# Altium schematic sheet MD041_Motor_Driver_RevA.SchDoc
size 431 x 279 mm; Date: Not shown in title block; ApprovedBy: Not shown in title block; CheckedBy: Not shown in title block; Author: Not shown in title block; CompanyName: Not shown in title block; Engineer: Not shown in title block; Organization: Not shown in title block; Address1: Not shown in title block; Address2: Not shown in title block; Address3: Not shown in title block; Address4: Not shown in title block; DocumentNumber: 2; Revision: Use project parameter SCH_Rev; SheetNumber: 1; SheetTotal: 4; PageSetup: Record=PageOptions¦CenterHorizontal=True¦CenterVertical=True¦PrintScale=1.00¦XCorrection=1.00¦YCorrection=1.00¦PrintKind=0¦BorderSize=5000000¦LeftOffset=0¦BottomOffset=0¦Orientation=2¦PaperLength=1000¦PaperWidth=1000¦Scale=100¦PaperSource=15¦PrintQuality=600¦MediaType=1¦DitherType=10¦PaperKind=Letter¦PrintScaleMode=1
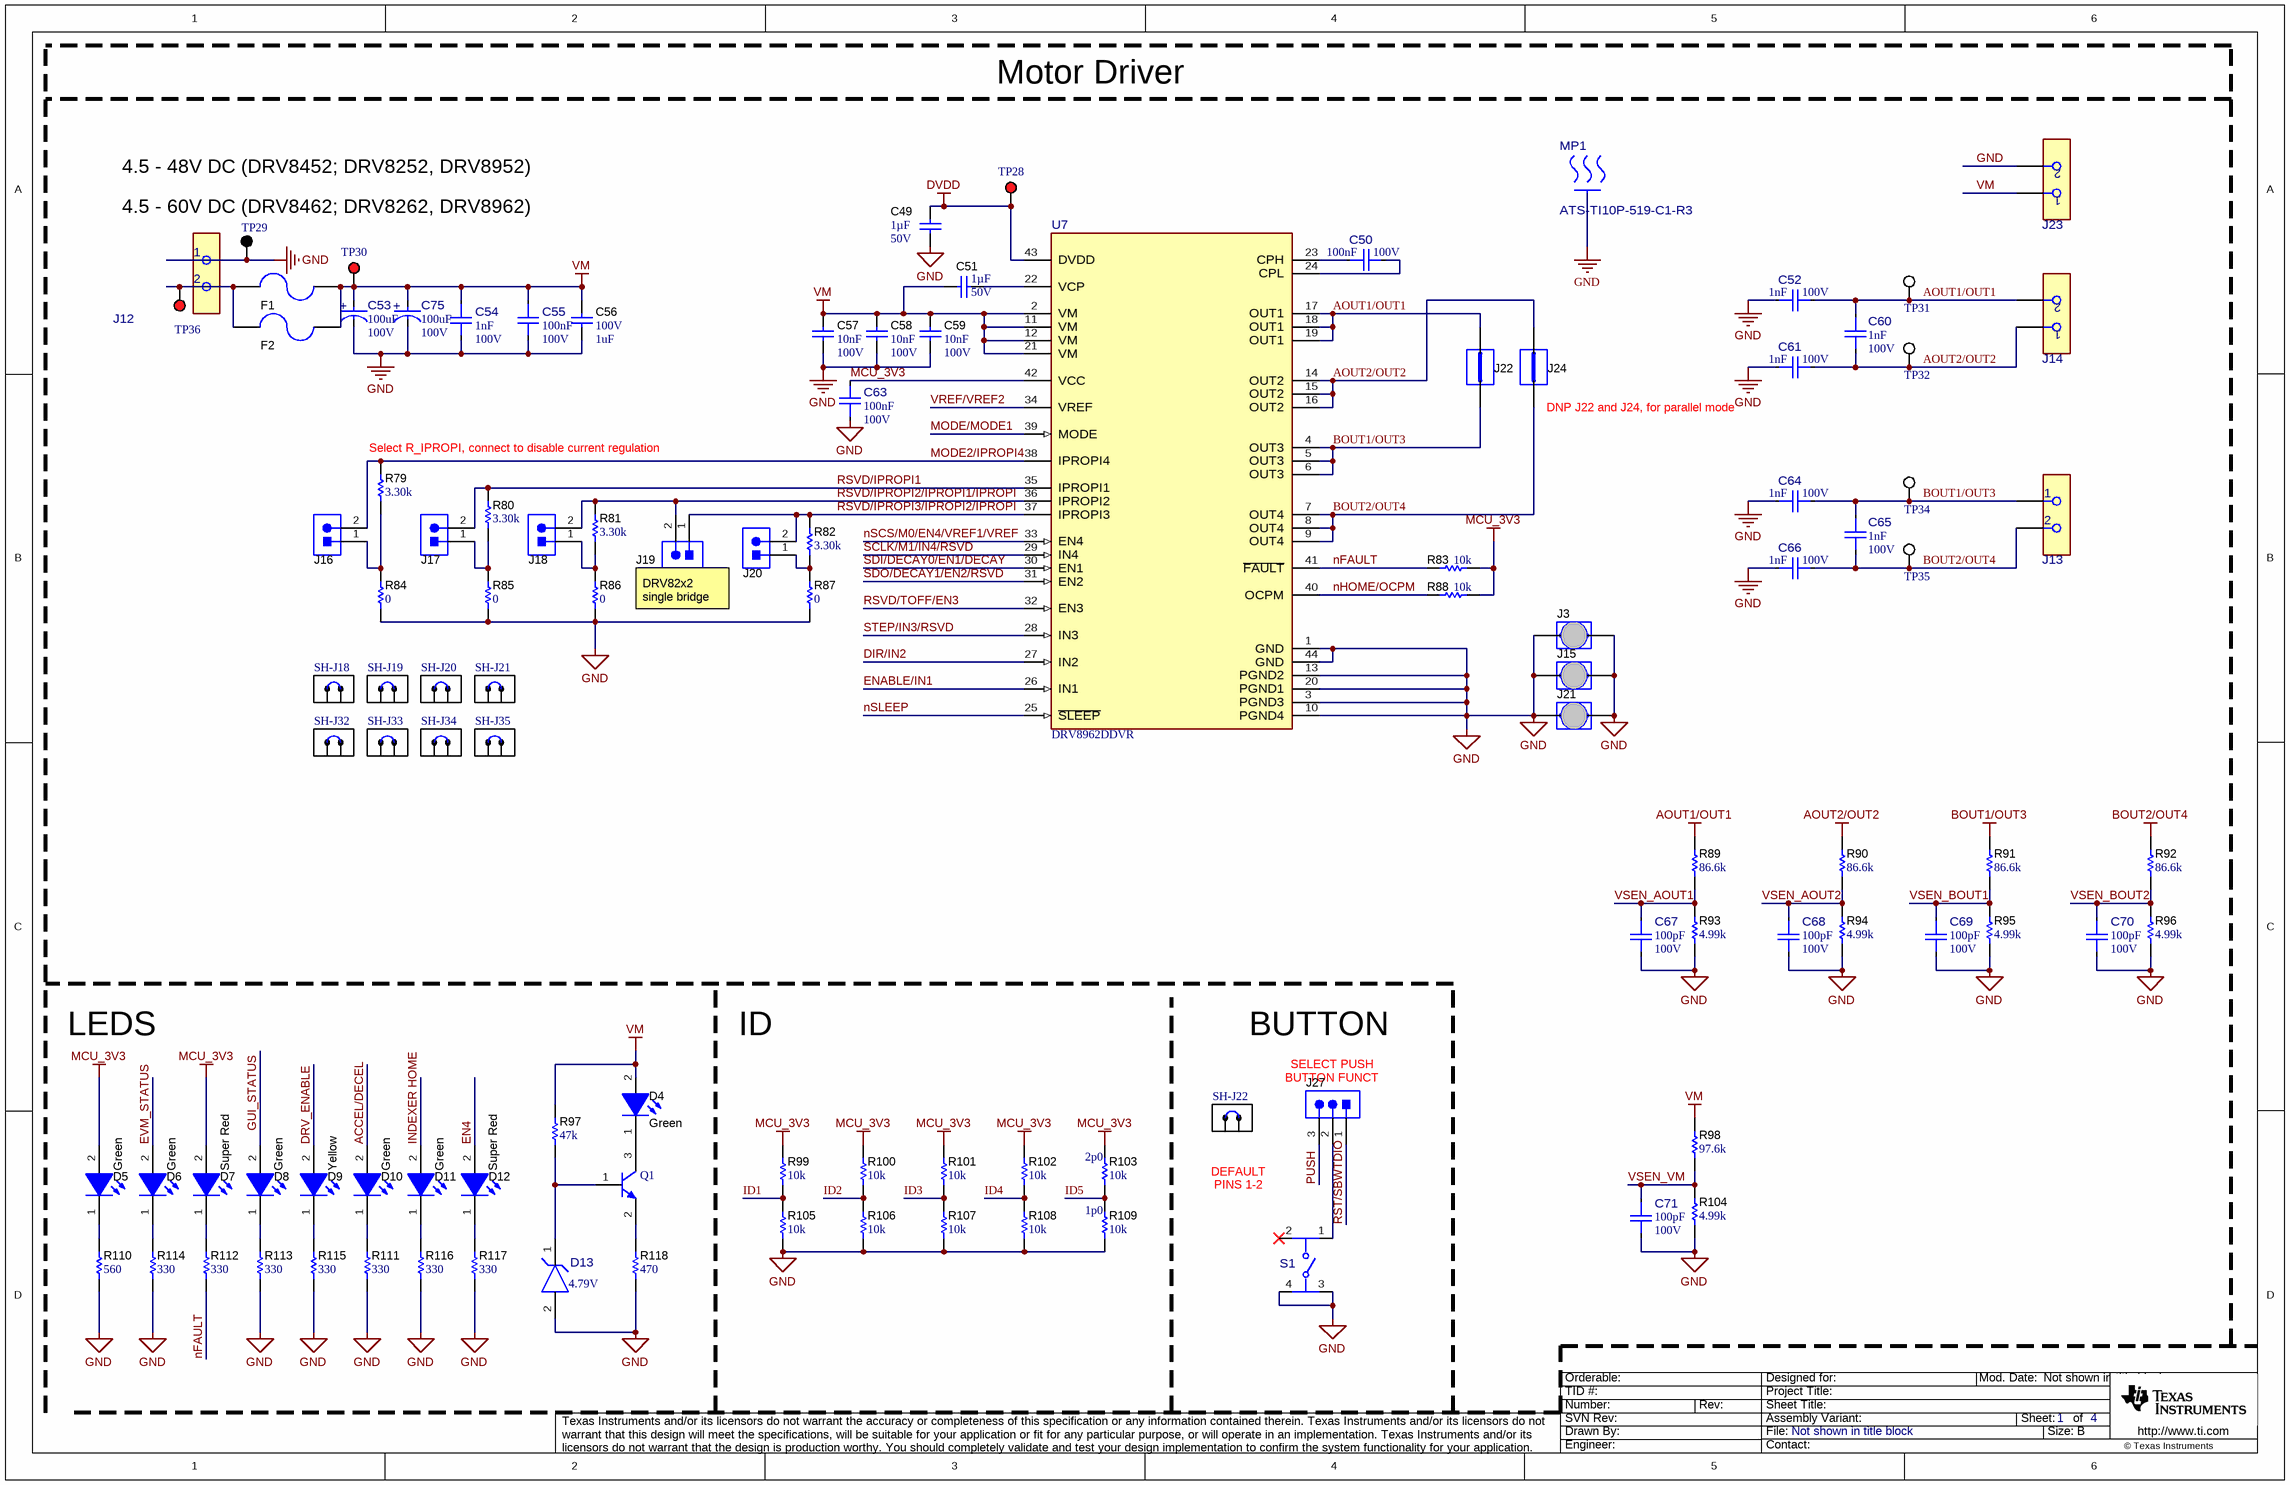
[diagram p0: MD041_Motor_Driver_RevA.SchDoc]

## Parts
C49  Cap_F: 1µF  VDC_V: 50V  [0805_HV]  (hidden comment: C2012X7R1H105K125AB)
C50  Cap_F: 100nF  VDC_V: 100V  [FP-885012206120_0603-MFG]  (hidden comment: 885012206120)
C51  Cap_F: 1µF  VDC_V: 50V  [0805_HV]  (hidden comment: C2012X7R1H105K125AB)
C52  ValueDisplayed: 1nF  VDC_V: 100V  [FP-885012006085_0603-MFG]  (hidden comment: 885012006085)
C53  ValueDisplayed: 100uF  VDC_V: 100V  [FP-EMVY101ARA101MKE0S_RADIAL-MFG]  (hidden comment: EMVY101ARA101MKE0S)
C54  ValueDisplayed: 1nF  VDC_V: 100V  [FP-885012006085_0603-MFG]  (hidden comment: 885012006085)
C55  Cap_F: 100nF  VDC_V: 100V  [FP-885012206120_0603-MFG]  (hidden comment: 885012206120)
C56  VDC_V: 100V  ValueDisplayed: 1uF  [1210_220]  (hidden comment: CGA6M2X7R2A105K200AA)
C57  Cap_F: 10nF  VDC_V: 100V  [0603L]  (hidden comment: 885012206114)
C58  Cap_F: 10nF  VDC_V: 100V  [0603L]  (hidden comment: 885012206114)
C59  Cap_F: 10nF  VDC_V: 100V  [0603L]  (hidden comment: 885012206114)
C60  ValueDisplayed: 1nF  VDC_V: 100V  [FP-885012006085_0603-MFG]  (hidden comment: 885012006085)
C61  ValueDisplayed: 1nF  VDC_V: 100V  [FP-885012006085_0603-MFG]  (hidden comment: 885012006085)
C63  Cap_F: 100nF  VDC_V: 100V  [FP-885012206120_0603-MFG]  (hidden comment: 885012206120)
C64  ValueDisplayed: 1nF  VDC_V: 100V  [FP-885012006085_0603-MFG]  (hidden comment: 885012006085)
C65  ValueDisplayed: 1nF  VDC_V: 100V  [FP-885012006085_0603-MFG]  (hidden comment: 885012006085)
C66  ValueDisplayed: 1nF  VDC_V: 100V  [FP-885012006085_0603-MFG]  (hidden comment: 885012006085)
C67  ValueDisplayed: 100pF  VDC_V: 100V  [FP-885012005080_0402-MFG]  (hidden comment: 885012005080)
C68  ValueDisplayed: 100pF  VDC_V: 100V  [FP-885012005080_0402-MFG]  (hidden comment: 885012005080)
C69  ValueDisplayed: 100pF  VDC_V: 100V  [FP-885012005080_0402-MFG]  (hidden comment: 885012005080)
C70  ValueDisplayed: 100pF  VDC_V: 100V  [FP-885012005080_0402-MFG]  (hidden comment: 885012005080)
C71  ValueDisplayed: 100pF  VDC_V: 100V  [FP-885012005080_0402-MFG]  (hidden comment: 885012005080)
C75  ValueDisplayed: 100uF  VDC_V: 100V  [FP-EMVY101ARA101MKE0S_RADIAL-MFG]  (hidden comment: EMVY101ARA101MKE0S)
D4  value Green  [WL-SMCW_GREEN]  (hidden comment: 150060VS75000)
D5  value Green  [WL-SMCW_GREEN]  (hidden comment: 150060VS75000)
D6  value Green  [WL-SMCW_GREEN]  (hidden comment: 150060VS75000)
D7  value Super Red  [WL-SMCW_RED]  (hidden comment: 150060SS75000)
D8  value Green  [WL-SMCW_GREEN]  (hidden comment: 150060VS75000)
D9  value Yellow  [WL-SMCW_YELLOW]  (hidden comment: 150060YS75000)
D10  value Green  [WL-SMCW_GREEN]  (hidden comment: 150060VS75000)
D11  value Green  [WL-SMCW_GREEN]  (hidden comment: 150060VS75000)
D12  value Super Red  [WL-SMCW_RED]  (hidden comment: 150060SS75000)
D13  Vf_V: 4.79V  [FP-BZX84J-B4V7,115_SC90-MFG]  (hidden comment: BZX84J-B4V7,115)
F1  0463015.ER  [Fuse_0463]  (value not drawn)
F2  0463015.ER  [Fuse_0463]  (value not drawn)
J3  D3082-05  [Harwin_D3082-05]  (value not drawn)
J12  691256610002  [FP-691256610002_HDR2-MFG]  (value not drawn)
J13  691250610002  [FP-691250610002_CONN_TERM_BLOCK2-MFG]  (value not drawn)
J14  691250610002  [FP-691250610002_CONN_TERM_BLOCK2-MFG]  (value not drawn)
J15  D3082-05  [Harwin_D3082-05]  (value not drawn)
J16  PBC02SAAN  [Sullins_PBC02SAAN]  (value not drawn)
J17  PBC02SAAN  [Sullins_PBC02SAAN]  (value not drawn)
J18  PBC02SAAN  [Sullins_PBC02SAAN]  (value not drawn)
J19  PBC02SAAN  [Sullins_PBC02SAAN]  (value not drawn)
J20  PBC02SAAN  [Sullins_PBC02SAAN]  (value not drawn)
J21  D3082-05  [Harwin_D3082-05]  (value not drawn)
J22  D3082-05  [Harwin_D3082-05]  (value not drawn)
J23  691250610002  [FP-691250610002_CONN_TERM_BLOCK2-MFG]  (value not drawn)
J24  D3082-05  [Harwin_D3082-05]  (value not drawn)
J27  61300311121  [WURTH_61300311121]  (value not drawn)
MP1  ATS-TI10P-519-C1-R3  [FP-ATS-TI10P-519-C1-R3_HEAT_SINK-MFG]
Q1  BC846BLT1G  [ONSC-SOT-23-3-318-08_V]  (value not drawn)
R79  ValueDisplayed: 3.30k  [0402L]  (hidden comment: ERJ-2RKF3301X)
R80  ValueDisplayed: 3.30k  [0402L]  (hidden comment: ERJ-2RKF3301X)
R81  ValueDisplayed: 3.30k  [0402L]  (hidden comment: ERJ-2RKF3301X)
R82  ValueDisplayed: 3.30k  [0402L]  (hidden comment: ERJ-2RKF3301X)
R83  ValueDisplayed: 10k  [0603L]  (hidden comment: RC0603JR-0710KL)
R84  ValueDisplayed: 0  [0402]  (hidden comment: CRCW04020000Z0EDHP)
R85  ValueDisplayed: 0  [0402]  (hidden comment: CRCW04020000Z0EDHP)
R86  ValueDisplayed: 0  [0402]  (hidden comment: CRCW04020000Z0EDHP)
R87  ValueDisplayed: 0  [0402]  (hidden comment: CRCW04020000Z0EDHP)
R88  ValueDisplayed: 10k  [0603L]  (hidden comment: RC0603JR-0710KL)
R89  ValueDisplayed: 86.6k  [0603L]  (hidden comment: CRCW060386K6FKEA)
R90  ValueDisplayed: 86.6k  [0603L]  (hidden comment: CRCW060386K6FKEA)
R91  ValueDisplayed: 86.6k  [0603L]  (hidden comment: CRCW060386K6FKEA)
R92  ValueDisplayed: 86.6k  [0603L]  (hidden comment: CRCW060386K6FKEA)
R93  ValueDisplayed: 4.99k  [0603L]  (hidden comment: CRCW06034K99FKEA)
R94  ValueDisplayed: 4.99k  [0603L]  (hidden comment: CRCW06034K99FKEA)
R95  ValueDisplayed: 4.99k  [0603L]  (hidden comment: CRCW06034K99FKEA)
R96  ValueDisplayed: 4.99k  [0603L]  (hidden comment: CRCW06034K99FKEA)
R97  ValueDisplayed: 47k  [0402]  (hidden comment: CRCW040247K0JNED)
R98  ValueDisplayed: 97.6k  [0603]  (hidden comment: CRCW060397K6FKEA)
R99  ValueDisplayed: 10k  [0603L]  (hidden comment: RC0603JR-0710KL)
R100  ValueDisplayed: 10k  [0603L]  (hidden comment: RC0603JR-0710KL)
R101  ValueDisplayed: 10k  [0603L]  (hidden comment: RC0603JR-0710KL)
R102  ValueDisplayed: 10k  [0603L]  (hidden comment: RC0603JR-0710KL)
R103  ValueDisplayed: 10k  [0603L]  (hidden comment: RC0603JR-0710KL)
R104  ValueDisplayed: 4.99k  [0603L]  (hidden comment: CRCW06034K99FKEA)
R105  ValueDisplayed: 10k  [0603L]  (hidden comment: RC0603JR-0710KL)
R106  ValueDisplayed: 10k  [0603L]  (hidden comment: RC0603JR-0710KL)
R107  ValueDisplayed: 10k  [0603L]  (hidden comment: RC0603JR-0710KL)
R108  ValueDisplayed: 10k  [0603L]  (hidden comment: RC0603JR-0710KL)
R109  ValueDisplayed: 10k  [0603L]  (hidden comment: RC0603JR-0710KL)
R110  ValueDisplayed: 560  [0603]  (hidden comment: RC0603FR-07560RL)
R111  ValueDisplayed: 330  [0603L]  (hidden comment: Resistor)
R112  ValueDisplayed: 330  [0603L]  (hidden comment: Resistor)
R113  ValueDisplayed: 330  [0603L]  (hidden comment: Resistor)
R114  ValueDisplayed: 330  [0603L]  (hidden comment: Resistor)
R115  ValueDisplayed: 330  [0603L]  (hidden comment: Resistor)
R116  ValueDisplayed: 330  [0603L]  (hidden comment: Resistor)
R117  ValueDisplayed: 330  [0603L]  (hidden comment: Resistor)
R118  ValueDisplayed: 470  [0603]  (hidden comment: RC0603FR-07470RL)
S1  430481025816  [FP-430481025816_SMT_SW_6MM2_6MM2-MFG]  (value not drawn)
SH-J18  60900213421  [Wurth_60900213421]  (value not drawn)
SH-J19  60900213421  [Wurth_60900213421]  (value not drawn)
SH-J20  60900213421  [Wurth_60900213421]  (value not drawn)
SH-J21  60900213421  [Wurth_60900213421]  (value not drawn)
SH-J22  60900213421  [Wurth_60900213421]  (value not drawn)
SH-J32  60900213421  [Wurth_60900213421]  (value not drawn)
SH-J33  60900213421  [Wurth_60900213421]  (value not drawn)
SH-J34  60900213421  [Wurth_60900213421]  (value not drawn)
SH-J35  60900213421  [Wurth_60900213421]  (value not drawn)
TP28  5010  [Keystone5010]  (value not drawn)
TP29  5011  [Keystone5011]  (value not drawn)
TP30  5010  [Keystone5010]  (value not drawn)
TP31  5015  [Testpoint_Keystone_Miniature]  (value not drawn)
TP32  5015  [Testpoint_Keystone_Miniature]  (value not drawn)
TP34  5015  [Testpoint_Keystone_Miniature]  (value not drawn)
TP35  5015  [Testpoint_Keystone_Miniature]  (value not drawn)
TP36  5010  [Keystone5010]  (value not drawn)
U7  DRV8962DDVR  [DDV0044E-MFG]

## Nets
AOUT1/OUT1: C52.2 C60.1 J14.2 J22.2 R89.2 TP31.1 U7.17(OUT1) U7.18(OUT1) U7.19(OUT1)
AOUT2/OUT2: C60.2 C61.2 J14.1 J24.2 R90.2 TP32.1 U7.14(OUT2) U7.15(OUT2) U7.16(OUT2)
BOUT1/OUT3: C64.2 C65.1 J13.1 J22.1 R91.2 TP34.1 U7.4(OUT3) U7.5(OUT3) U7.6(OUT3)
BOUT2/OUT4: C65.2 C66.2 J13.2 J24.1 R92.2 TP35.1 U7.7(OUT4) U7.8(OUT4) U7.9(OUT4)
DVDD: C49.2 TP28.1 U7.43(DVDD)
GND: C49.1 C52.1 C53.1(CATHODE) C54.2 C55.2 C56.2 C57.2 C58.2 C59.2 C61.1 C63.1 C64.1 C66.1 C67.2 C68.2 C69.2 C70.2 C71.2 C75.1(CATHODE) D13.2(anode) J3.1 J3.2 J12.1 J15.1 J15.2 J21.1 J21.2 J23.2 R84.1 R85.1 R86.1 R87.1 R93.1 R94.1 R95.1 R96.1 R104.1 R105.2 R106.2 R107.2 R108.2 R109.2 R110.1 R111.1 R113.1 R114.1 R115.1 R116.1 R117.1 R118.1 S1.3 S1.4 TP29.1 U7.1(GND) U7.3(PGND3) U7.10(PGND4) U7.13(PGND2) U7.20(PGND1) U7.44(GND)
MCU_3V3: C63.2 D5.2(A) D7.2(A) R83.2 R88.2 R99.1 R100.1 R101.1 R102.1 R103.1 U7.42(VCC)
VM: C51.2 C53.2(ANODE) C54.1 C55.1 C56.1 C57.1 C58.1 C59.1 C75.2(ANODE) D4.2(A) F1.1 F2.1 J23.1 R97.2 R98.2 TP30.1 U7.2(VM) U7.11(VM) U7.12(VM) U7.21(VM)
ACCEL/DECEL: D10.2(A)
DIR/IN2: U7.27(IN2)
DRV_ENABLE: D9.2(A)
EN4: D12.2(A)
ENABLE/IN1: U7.26(IN1)
EVM_STATUS: D6.2(A)
GUI_STATUS: D8.2(A)
ID1: R99.2 R105.1
ID2: R100.2 R106.1
ID3: R101.2 R107.1
ID4: R102.2 R108.1
ID5: R103.2 R109.1
INDEXER HOME: D11.2(A)
MODE2/IPROPI4: J16.2 R79.2 U7.38(IPROPI4)
MODE/MODE1: U7.39(MODE)
nFAULT: R83.1 R112.1 U7.41(~{FAULT})
nHOME/OCPM: R88.1 U7.40(OCPM)
nSCS/M0/EN4/VREF1/VREF: U7.33(EN4)
nSLEEP: U7.25(~{SLEEP})
PUSH: J27.3
RST/SBWTDIO: J27.1
RSVD/IPROPI1: J17.2 R80.2 U7.35(IPROPI1)
RSVD/IPROPI2/IPROPI1/IPROPI: J18.2 J19.2 R81.2 U7.36(IPROPI2)
RSVD/IPROPI3/IPROPI2/IPROPI: J19.1 J20.2 R82.2 U7.37(IPROPI3)
RSVD/TOFF/EN3: U7.32(EN3)
SCLK/M1/IN4/RSVD: U7.29(IN4)
SDI/DECAY0/EN1/DECAY: U7.30(EN1)
SDO/DECAY1/EN2/RSVD: U7.31(EN2)
STEP/IN3/RSVD: U7.28(IN3)
VREF/VREF2: U7.34(VREF)
VSEN_AOUT1: C67.1 R89.1 R93.2
VSEN_AOUT2: C68.1 R90.1 R94.2
VSEN_BOUT1: C69.1 R91.1 R95.2
VSEN_BOUT2: C70.1 R92.1 R96.2
VSEN_VM: C71.1 R98.1 R104.2
NetC50_1: C50.1 U7.23(CPH)
NetC50_2: C50.2 U7.24(CPL)
NetC51_1: C51.1 U7.22(VCP)
NetD4_1: D4.1(K) Q1.3(C)
NetD5_1: D5.1(K) R110.2
NetD6_1: D6.1(K) R114.2
NetD7_1: D7.1(K) R112.2
NetD8_1: D8.1(K) R113.2
NetD9_1: D9.1(K) R115.2
NetD10_1: D10.1(K) R111.2
NetD11_1: D11.1(K) R116.2
NetD12_1: D12.1(K) R117.2
NetD13_1: D13.1(cathode) Q1.1(B) R97.1
NetF1_2: F1.2 F2.2 J12.2 TP36.1
NetJ16_1: J16.1 R79.1 R84.2
NetJ17_1: J17.1 R80.1 R85.2
NetJ18_1: J18.1 R81.1 R86.2
NetJ20_1: J20.1 R82.1 R87.2
NetJ27_2: J27.2 S1.1
NetQ1_2: Q1.2(E) R118.2

Not connected (* = marked no-connect by the designer): S1 2*

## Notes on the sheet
- Motor Driver
- 4.5 - 48V DC (DRV8452; DRV8252, DRV8952)
- 4.5 - 60V DC (DRV8462; DRV8262, DRV8962)
- (near J24) DNP J22 and J24, for parallel mode
- (near R79) Select R_IPROPI, connect to disable current regulation
- DRV82x2 single bridge
- LEDS
- ID
- BUTTON
- (near J27) SELECT PUSH
- (near J27) BUTTON FUNCT
- (near R103) 2p0
- (near SH-J22) DEFAULT
- (near R109) 1p0
- PINS 1-2

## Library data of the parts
C49 C51 = CMP-0007873-2: CAP, CERM, 1 uF, 50 V, +/- 10%, X7R, 0805; Manufacturer: TDK; TaMin_C: -55°C; ESR_ohm: 8.782m; Polarized: N; SizeAreaWB_mm2: 6.75; Value1: 0.008782 ohm; U/M: EA; Value: 1uF; TaMax_C: 125°C; SizeZ_mm: 1.45; SizeX_mm: 2; SizeY_mm: 1.25; Cap_Case: 0805; SizeArea_mm2: 2.5; IRMS_A: 2.2049A; AEC Category: Q200
C50 C55 C63 = CMP-0095152-1: 0.1 µF ±10% 100V Ceramic Capacitor X7R 0603 (1608 Metric); Manufacturer: Wurth Electronics; Value: 100nF; SizeZ_mm: 0.87mm; AEC Qualified: No; TempCo: 15%
C52 C54 C60 C61 C64-C66 = CMP-0097311-1: 1000 pF ±5% 100V Ceramic Capacitor C0G, NP0 0603 (1608 Metric); Manufacturer: Wurth Electronics; TempCo: 30ppm/°C; SizeZ_mm: 0.87mm; AEC Qualified: No; Value: 1nF
C53 C75 = CMP-0094051-1: 100uF 100V 20% Aluminum Electrolytic Capacitors Radial, Can - SMD - 5000 Hrs @ 105°C; Manufacturer: United Chemi-Con; Value: 100µF; IRMS_A: 450mA; Life: 5000Hours; SizeZ_mm: 14mm; AEC Grade: Grade 2; Leakage Current: 100uA; Dissipation Factor: 10%; AEC Qualified: Yes
C56 = CMP-0009145-2: CAP, CERM, 1 uF, 100 V, +/- 10%, X7R, AEC-Q200 Grade 1, 1210; Manufacturer: TDK; TaMin_C: -55°C; ESR_ohm: 4.956m; Polarized: N; SizeAreaWB_mm2: 14.7; Value1: 0.004956 ohm; U/M: EA; Value: 1uF; TaMax_C: 125°C; SizeZ_mm: 2.2; SizeX_mm: 3.2; SizeY_mm: 2.5; SizeArea_mm2: 8; AEC Qualified: Y; Cap_F: 1µF; IRMS_A: 3.3073A; AEC Grade: 1; AEC Category: Q200
C57-C59 = CMP-0079993-1: CAP, CERM, 0.01 µF, 100 V,+/- 10%, X7R, 0603; Manufacturer: Wurth Elektronik; Polarized: N; Value: 0.01uF; ValueDisplayed: 0.01µF; U/M: EA; TaMin_C: -55°C; TaMax_C: 105°C; Cap_Case: 0603; SizeX_mm: 1.6; SizeArea_mm2: 1.28; AEC Category: Q200; SizeZ_mm: 1; SizeAreaWB_mm2: 4.68; SizeY_mm: 0.8
C67-C71 = CMP-0097308-1: 100 pF ±5% 100V Ceramic Capacitor C0G, NP0 0402 (1005 Metric); Manufacturer: Wurth Electronics; Value: 100pF; SizeZ_mm: 0.55mm; TempCo: 30ppm/°C; AEC Qualified: No
D4-D6 D8 D10 D11 = CMP-0002894-2: LED, Green, SMD; Manufacturer: Wurth Elektronik; Type: AlInGaP; Value2: 2V; Io_A: 20mA; Value1: W
D7 D12 = CMP-0002893-1: LED, Super Red, SMD; Manufacturer: Wurth Elektronik; Io_A: 20mA; Value1: W; U/M: EA; Vf_V: 1.9V; Type: AlInGaP
D9 = CMP-0002892-3: LED, Yellow, SMD; Manufacturer: Wurth Elektronik; Value1: W; Vf_V: 2V; Type: AlInGaP; Io_A: 20mA
D13 = CMP-0097377-1: Diode Zener Single 4.7V 2% 550mW Automotive 2-Pin SOD-323F T/R; Manufacturer: Nexperia; TaMin_C: -55°C; Vr_V: 2V; SizeZ_mm: 0.8mm; Max Reverse Leakage Current: 3uA; TJmax_C: 150°C; Zener Impedance: 80Ω; AEC Grade: Grade 0; Forward Current: 250mA; TaMax_C: +150°C; AEC Qualified: Yes
F1 F2 = CMP-0081016-1: Fuse, 15 A, 250 VAC, 100 VDC, SMD; Manufacturer: Littelfuse; TaMin_C: -55°C; Irating_A: 15A; SizeAreaWB_mm2: 61.952; Interrupt_AC: 100A; Interrupt_DC: 50A; VAC_V: 250V; TaMax_C: 125°C; Fuse Speed: Fast; SizeZ_mm: 3.12; SizeX_mm: 10.1; SizeArea_mm2: 31.512; VDC_V: 100V; Fuse Technology: Board Mount; Rtyp_Ohm: 4.7m; MeltingTyp: 142
J3 J15 J21 J22 J24 = CMP-0075110-1: 1mm Uninsulated Shorting Plug, 10.16mm spacing, TH; Manufacturer: Harwin; CNHeader: False; Green_Lifecycle: Active; Green_REACh: Passed; CompType: Jumper Wire
J12 = CMP-0086764-1: 2 Position Wire to Board Terminal Block Horizontal with Board 0.400" (10.16mm) Through Hole; Manufacturer: Wurth; Current_A: 57A; Voltage_V: 750V; ContactFinish: Zinc; Row_Count: 1
J13 J14 J23 = CMP-0093233-2: 2 Position Wire to Board Terminal Block Horizontal with Board 0.250" (6.35mm) Through Hole; Manufacturer: Wurth Electronics; Current_A: 32A; Conn Gender: Female; Row_Count: 1; ContactFinish: Zinc; SizeZ_mm: 21.6mm; Max Wire Gauge: 10; Min Wire Gauge: 30; Voltage_V: 450V; AEC Qualified: No; Is Female: yes
J16-J20 = CMP-0054566-1: Header, 100mil, 2x1, Gold, TH; Manufacturer: Sullins Connector Solutions; CNHeader: TRUE; Current_A: 3A; Green_Lifecycle: Active; Shrouded: N; Gender: Male; Green_REACh: Passed; Voltage_V: 1.8kV; Row_Count: 1; Pitch_mm: 2.54; CT: FALSE; Cert_UL: Y
J27 = CMP-0054796-4: Header, 2.54 mm, 3x1, Gold, TH; Manufacturer: Wurth Elektronik; Green_Lifecycle: Active; Green_REACh: Passed; CT: FALSE; CNHeader: TRUE
MP1 = CMP-0096184-1: Heat Sink Aluminum Top Mount; Manufacturer: Advanced Thermal Solutions; AEC Qualified: No; Thermal Resistance Forced Air Flow: 2.2°C/W; SizeZ_mm: 35.6mm; Standoff Height: 1.6mm
Q1 = CMP-1048-00779-1: General Purpose Transistor, NPN Silicon, 3-Pin SOT-23, Pb-Free, Tape and Reel; Manufacturer: On Semiconductor; fT Min (MHz): 100; IC Continuous (A): 0.1
R79-R82 = CMP-0026695-1: RES, 3.30 k, 1%, 0.1 W, AEC-Q200 Grade 0, 0402; Manufacturer: Panasonic; Power_W: 100mW; TempCo: 100 ppm/C; Value_Code: 3k30; U/M: EA; Value: 3.30k; Res_ohm: 3.3k; SizeX_mm: 1; SizeY_mm: 0.5; SizeZ_mm: 0.6; Value2: 0.1W; AEC Qualified: Y; VDC_V: 50V; AEC Grade: 0; AEC Category: Q200
R83 R88 R99-R103 R105-R109 = CMP-0025886-5: RES, 10 k, 5%, 0.1 W, 0603; Manufacturer: Yageo; Power_W: 100mW; TempCo: 100 ppm/C; Value_Code: 10k0; Value: 10k; EIA_Code: E24; SizeX_mm: 1.6; SizeY_mm: 0.8; SizeZ_mm: 1; Value2: 0.1W; SizeArea_mm2: 1.28; AEC Qualified: N; VDC_V: 75V; AEC Category: Q200; SizeAreaWB_mm2: 4.68
R84-R87 = CMP-0081856-1: RES, 0, 0%, 0.2 W, AEC-Q200 Grade 0, 0402; Manufacturer: Vishay-Dale; SizeAreaWB_mm2: 3; SizeArea_mm2: 0.5; AEC Qualified: Y; AEC Category: Q200; Value: 0; SizeZ_mm: 0.6; Power_W: 200mW; VDC_V: 50V; Value2: 0.2W; SizeX_mm: 1
R89-R92 = CMP-0022628-4: RES, 86.6 k, 1%, 0.1 W, AEC-Q200 Grade 0, 0603; Manufacturer: Vishay-Dale; Value: 86.6k; Value_Code: 86k6; Power_W: 100mW; Value2: 0.1W; VDC_V: 75V; TempCo: 100 ppm/C; EIA_Code: E96; AEC Category: Q200; AEC Qualified: Y; AEC Grade: 0; SizeY_mm: 0.8; SizeZ_mm: 1; SizeArea_mm2: 1.28; SizeX_mm: 1.6
R93-R96 R104 = CMP-0022458-4: RES, 4.99 k, 1%, 0.1 W, AEC-Q200 Grade 0, 0603; Manufacturer: Vishay-Dale; Value: 4.99k; Value_Code: 4k99; Power_W: 100mW; Value2: 0.1W; VDC_V: 75V; TempCo: 100 ppm/C; EIA_Code: E96; SizeX_mm: 1.6; SizeY_mm: 0.8; SizeZ_mm: 1; SizeArea_mm2: 1.28; AEC Qualified: Y; AEC Category: Q200; AEC Grade: 0
R97 = CMP-0026935-3: RES, 47 k, 5%, 0.063 W, AEC-Q200 Grade 0, 0402; Manufacturer: Vishay-Dale; Power_W: 63mW; TempCo: 200 ppm/C; Value_Code: 47k0; Value: 47k; EIA_Code: E24; SizeX_mm: 1; SizeY_mm: 0.5; SizeZ_mm: 0.6; Value2: 0.063W; AEC Qualified: Y; VDC_V: 50V; AEC Category: Q200; AEC Grade: 0
R98 = CMP-0022663-4: RES, 97.6 k, 1%, 0.1 W, AEC-Q200 Grade 0, 0603; Manufacturer: Vishay-Dale; Value: 97.6k; Value_Code: 97k6; Power_W: 100mW; Value2: 0.1W; VDC_V: 75V; TempCo: 100 ppm/C; EIA_Code: E96; AEC Category: Q200; AEC Qualified: Y; AEC Grade: 0; SizeY_mm: 0.8; SizeZ_mm: 1; SizeArea_mm2: 1.28; SizeX_mm: 1.6
R110 = CMP-0023183-5: RES, 560, 1%, 0.1 W, 0603; Manufacturer: Yageo; Power_W: 100mW; TempCo: 100 ppm/C; Value_Code: 560R; Value: 560; SizeX_mm: 1.6; SizeY_mm: 0.8; SizeZ_mm: 1; Value2: 0.1W; SizeArea_mm2: 1.28; AEC Qualified: N; VDC_V: 75V; AEC Category: Q200; SizeAreaWB_mm2: 4.68
R111-R117 = CMP-0025785-4: RES, 330, 5%, 0.1 W, AEC-Q200 Grade 0, 0603; PartNumber: CRCW0603330RJNEA; Manufacturer: Vishay-Dale; Value: 330; Value_Code: 330R; Power_W: 100mW; Value2: 0.1W; VDC_V: 75V; TempCo: 200 ppm/C; EIA_Code: E24; AEC Category: Q200; AEC Qualified: Y; AEC Grade: 0; SizeX_mm: 1.6; SizeY_mm: 0.8; SizeZ_mm: 1; SizeArea_mm2: 1.28
R118 = CMP-0023129-5: RES, 470, 1%, 0.1 W, 0603; Manufacturer: Yageo; Power_W: 100mW; TempCo: 100 ppm/C; Value_Code: 470R; Value: 470; SizeX_mm: 1.6; SizeY_mm: 0.8; SizeZ_mm: 1; Value2: 0.1W; SizeArea_mm2: 1.28; AEC Qualified: N; VDC_V: 75V; AEC Category: Q200; SizeAreaWB_mm2: 4.68
S1 = CMP-0097347-1: Tactile Switch SPST-NO Top Actuated Surface Mount; Manufacturer: Wurth Electronics; VDC_V: 12V; Electromechanical Life: 1000000Cycles; SizeZ_mm: 2.7mm; Coil Resistance_ohm: 100mΩ; Operating Force: 160gf; AEC Qualified: No; Contact Current Rating: 50mA
SH-J18-SH-J22 SH-J32-SH-J35 = CMP-0003761-2: Shunt, 2.54mm, Gold, Black; Manufacturer: Wurth Elektronik
TP28 TP30 TP36 = CMP-0055147-2: Test Point, Multipurpose, Red, TH; Manufacturer: Keystone Electronics; CNHeader: FALSE; Green_Lifecycle: Active; Green_REACh: Passed; ContactFinish: Silver; CT: TRUE
TP29 = CMP-0055148-2: Test Point, Multipurpose, Black, TH; Manufacturer: Keystone Electronics; CNHeader: FALSE; Green_Lifecycle: Active; Green_REACh: Passed; ContactFinish: Silver; CT: TRUE
TP31 TP32 TP34 TP35 = CMP-0055152-2: Test Point, Miniature, SMT; Manufacturer: Keystone Electronics; CNHeader: FALSE; Green_Lifecycle: Active; Green_REACh: Passed; CT: TRUE
U7 = CMP-0094088-3: Quad Half-Bridge Motor Driver with Current Sense Output; Manufacturer: Texas Instruments; Standoff Height: 0.05mm; AEC Qualified: No; CompType: IC; Motor Type: Stepper; SizeZ_mm: 1.2mm; Min Supply Voltage: 4.5V; TaMax_C: +125°C; TaMin_C: -40°C; Max Supply Voltage: 60V; Number Of Outputs: 4; Nominal Supply Current: 3-7mA; TJmax_C: +150°C; Switching Frequency: 360kHz; AEC Category: Q200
